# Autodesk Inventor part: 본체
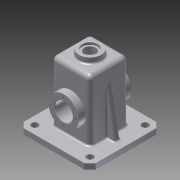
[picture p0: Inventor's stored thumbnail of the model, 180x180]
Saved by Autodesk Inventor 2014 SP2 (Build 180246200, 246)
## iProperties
Created: 2016-02
Part Number: 본체
Material: 알루미늄 6061
Document SubType Name: Modeling
Designer: 1sil_ho3333
Density: 2.71 g/cm^3
Appearance: 알루미늄 - 평지
Mass: 974.663 g
Surface Area: 1034.05 cm^2
Volume: 359.654 cm^3
Author: 1sil_ho3333
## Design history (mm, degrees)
sketch "스케치1"
  geometry: L1 (65, -65)-(-65, -65); L2 (-65, -65)-(-65, 65); L3 (-65, 65)-(65, 65); L4 (65, 65)-(65, -65); 1 further point
  constraints: 8 end point, 2 parallel, 1 horizontal, 1 perpendicular
  dimensions: "d0" = 130 distance of L2.end L3.end; "d1" = 130 distance of L3.end L1.start; "d2" = 65 distance from line of point (0, 0) L1; "d3" = 65 distance from line of point (0, 0) L2
extrude "돌출1" new body sketch "스케치1" distance "d4" = 10; taper "d5" = 0 deg
chamfer "모따기1" distance "d6" = 10; stored, may be unused: second distance "d7" = 2, angle "d8" = 45 deg
sketch "스케치2"
  geometry: L1 (35, -35)-(-35, -35); L2 (-35, -35)-(-35, 35); L3 (-35, 35)-(35, 35); L4 (35, 35)-(35, -35); 1 further point
  constraints: 8 end point, 2 parallel, 1 horizontal, 1 perpendicular
  dimensions: "d9" = 70 distance of L2.end L3.end; "d10" = 70 distance of L3.end L1.start; "d11" = 35 distance from line of point (0, 0) L1; "d12" = 35 distance from line of point (0, 0) L2
extrude "돌출2" join sketch "스케치2" distance "d13" = 110; taper "d14" = 0 deg
node "작업 평면1"
sketch "스케치3"
  geometry: C1 r 20 at (0, 0); 1 further point
  constraints: 1 centre point, 1 coincident
  dimensions: "d16" = 40 diameter of C1
extrude "돌출3" join sketch "스케치3" distance "d17" = 30; taper "d18" = 0 deg
node "작업 평면2"
sketch "스케치4"
  geometry: L1 (0, 0)-(0, 55); C1 r 27.5 at (0, 55)
  constraints: 2 end point, 1 centre point, 1 coincident, 1 vertical
  dimensions: "d20" = 55 distance of L1.start L1.end; "d21" = 55 diameter of C1
extrude "돌출4" join sketch "스케치4" distance "d22" = 30; taper "d23" = 0 deg
sketch "스케치6"
  geometry: L1 (30, 115)-(-30, 115); L2 (35, 10)-(35, 120) reference; L3 (-35, 10)-(-35, 120) reference; L4 (35, 120)-(-35, 120) reference; L5 (-55, 0)-(55, 0) reference; L6 (-55, 55)-(55, 55); L7 (-55, 82.5)-(55, 82.5); L8 (-55, 27.5)-(55, 27.5); L9 (-30, 82.5)-(-23, 75.5); L10 (-30, 27.5)-(-23, 34.5); L11 (-23, 34.5)-(-23, 75.5); L12 (-30, 0)-(-30, 27.5); L13 (-30, 82.5)-(-30, 115); L14 (0, 0)-(0, 115); L15 (30, 82.5)-(30, 115); L16 (30, 82.5)-(23, 75.5); L17 (23, 34.5)-(23, 75.5); L18 (30, 27.5)-(23, 34.5); L19 (30, 0)-(30, 27.5); L20 (30, 0)-(30, 27.5); L21 (30, 82.5)-(30, 115)
  constraints: 34 end point, 8 parallel, 6 point on line, 4 symmetric about line, 1 midpoint, 1 perpendicular
  dimensions: "d25" = 5 distance between parallel lines of L4 L1; "d27" = 55 distance between parallel lines of L5 L6; "d28" = 27.5 distance between parallel lines of L6 L7; "d29" = 55 distance between parallel lines of L8 L7; "d32" = 55 distance of L10.start L9.start; "d33" = 55 distance of L18.start L15.start (derived); "d34" = 58 distance between parallel lines of L2 L11; "d35" = 65 distance between parallel lines of L2 L13; "d36" = 20 distance from line of L7.end L2; "d37" = 20 distance from line of L6.end L2; "d38" = 20 distance from line of L8.end L2; "d39" = 90 distance from line of L7.start L2; "d40" = 90 distance from line of L6.start L2; "d41" = 90 distance from line of L8.start L2
extrude "돌출5" cut sketch "스케치6" stored distance "d42" = 60; taper "d43" = 0 deg
sketch "스케치7"
  geometry: C1 r 27.5 at (0, 0) reference; C2 r 16 at (0, 0); 1 further point
  constraints: 1 centre point, 1 coincident
  dimensions: "d44" = 32 diameter of C2
extrude "돌출6" cut sketch "스케치7" distance "d45" = 50; taper "d46" = 0 deg
sketch "스케치8"
  geometry: L1 (0, 0)-(0, 22.5); C1 r 27.5 at (0, 0) reference; 2 further points
  constraints: 2 end point, 1 coincident, 1 vertical
  dimensions: "d47" = 22.5 distance of L1.start L1.end
hole "구멍1" sketch "스케치8" at (0, 22.5) diameter "d48" = 3.459; stored, may be unused: countersink angle "d52" = 90 deg, drill point angle "d54" = 118 deg; dims "d49" = 8, "d50" = 4, "d51" = 2, "d53" = 10
node "작업 평면3"
sketch "스케치11"
  geometry: L1 (0, 0)-(0, 55); C1 r 27.5 at (0, 55)
  constraints: 2 end point, 1 centre point, 1 coincident, 1 vertical
  dimensions: "d59" = 55 distance of L1.start L1.end; "d60" = 55 diameter of C1
extrude "돌출7" join sketch "스케치11" distance "d61" = 15; taper "d62" = 0 deg
sketch "스케치14"
  geometry: C1 r 20 at (0, 0) reference; C2 r 14 at (0, 0)
  constraints: 1 centre point, 1 coincident
  dimensions: "d63" = 28 diameter of C2
extrude "돌출8" cut sketch "스케치14" distance "d64" = 4; taper "d65" = 0 deg
sketch "스케치15"
  geometry: C1 r 14 at (0, 0) reference; C2 r 10.5 at (0, 0)
  constraints: 1 centre point, 1 coincident
  dimensions: "d66" = 21 diameter of C2
extrude "돌출9" cut sketch "스케치15" distance "d67" = 50; taper "d68" = 0 deg
sketch "스케치16"
  geometry: L1 (65, 10)-(65, 0) reference; L2 (50, 10)-(50, 0); L3 (35, 10)-(35, 120) reference; L4 (50, 10)-(35, 95.069); L5 (50, 10)-(35, 10); L6 (35, 10)-(35, 95.069); 1 further point
  constraints: 8 end point, 2 perpendicular, 1 parallel, 1 point on line
  dimensions: "d69" = 15 distance between parallel lines of L1 L2; "d70" = 10 deg angle of L1 L4
extrude "돌출10" join sketch "스케치16" stored distance "d71" = 10; taper "d72" = 0 deg
fillet "모깎기1" dims "d73" = 8
fillet "모깎기2" dims "d74" = 8
fillet "모깎기3" dims "d75" = 3
fillet "모깎기4" dims "d76" = 3
sketch "스케치17"
  geometry: L1 (-55, -65)-(55, -65) reference; L2 (65, -55)-(65, 55) reference; L3 (-50, -50)-(50, -50); L4 (50, -50)-(50, 50); L5 (50, 50)-(-50, 50); L6 (-50, 50)-(-50, -50); C1 r 6 at (50, 50); C2 r 6 at (50, -50); C3 r 6 at (-50, -50); C4 r 6 at (-50, 50); 1 further point
  constraints: 8 end point, 4 centre point, 4 coincident, 3 equal radius, 2 parallel, 1 horizontal, 1 perpendicular
  dimensions: "d77" = 100 distance of L3.end L4.end; "d78" = 100 distance of L4.end L5.end; "d79" = 15 distance between parallel lines of L2 L4; "d80" = 15 distance between parallel lines of L1 L3; "d81" = 12 diameter of C1
extrude "돌출11" cut sketch "스케치17" distance "d82" = 15; taper "d83" = 0 deg
chamfer "모따기2" distance "d84" = 1; stored, may be unused: second distance "d85" = 2, angle "d86" = 45 deg
fillet "모깎기7" dims "d89" = 3
node "작업 평면4"
sketch "스케치18"
  geometry: L1 (-20, 130)-(20, 130) reference; L2 (35, 13)-(35, 112) reference; 2 further points
  constraints: 1 vertical alignment, 1 other
  dimensions: "d91" = 30 distance from line of L1 point (0, 100); "d92" = 35 distance from line of L2 point (0, 100) (derived)
feature "엠보싱1" sketch "스케치18" dims "d0" = 130, "d1" = 130, "d2" = 65, "d3" = 65, "d93" = 0.5, "d94" = 0
fillet "모깎기8" dims "d95" = 3
fillet "모깎기9" dims "d96" = 0.5
node "솔리드1"
pattern_circular "원형 패턴1" dims angle "d56" = 360 deg
mirror "대칭2"
mirror "대칭3"
other parameters: "d19" = -48, "d24" = 5, "d26" = 5, "d30" = 7, "d31" = 135 deg, "d58" = 48, "d90" = 72
